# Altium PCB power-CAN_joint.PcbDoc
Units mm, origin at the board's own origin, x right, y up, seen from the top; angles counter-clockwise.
Board outline 50 x 64 mm, 2 copper layers (Top Layer, Bottom Layer); 8 components, 5 nets, 42 pads, 3 vias.
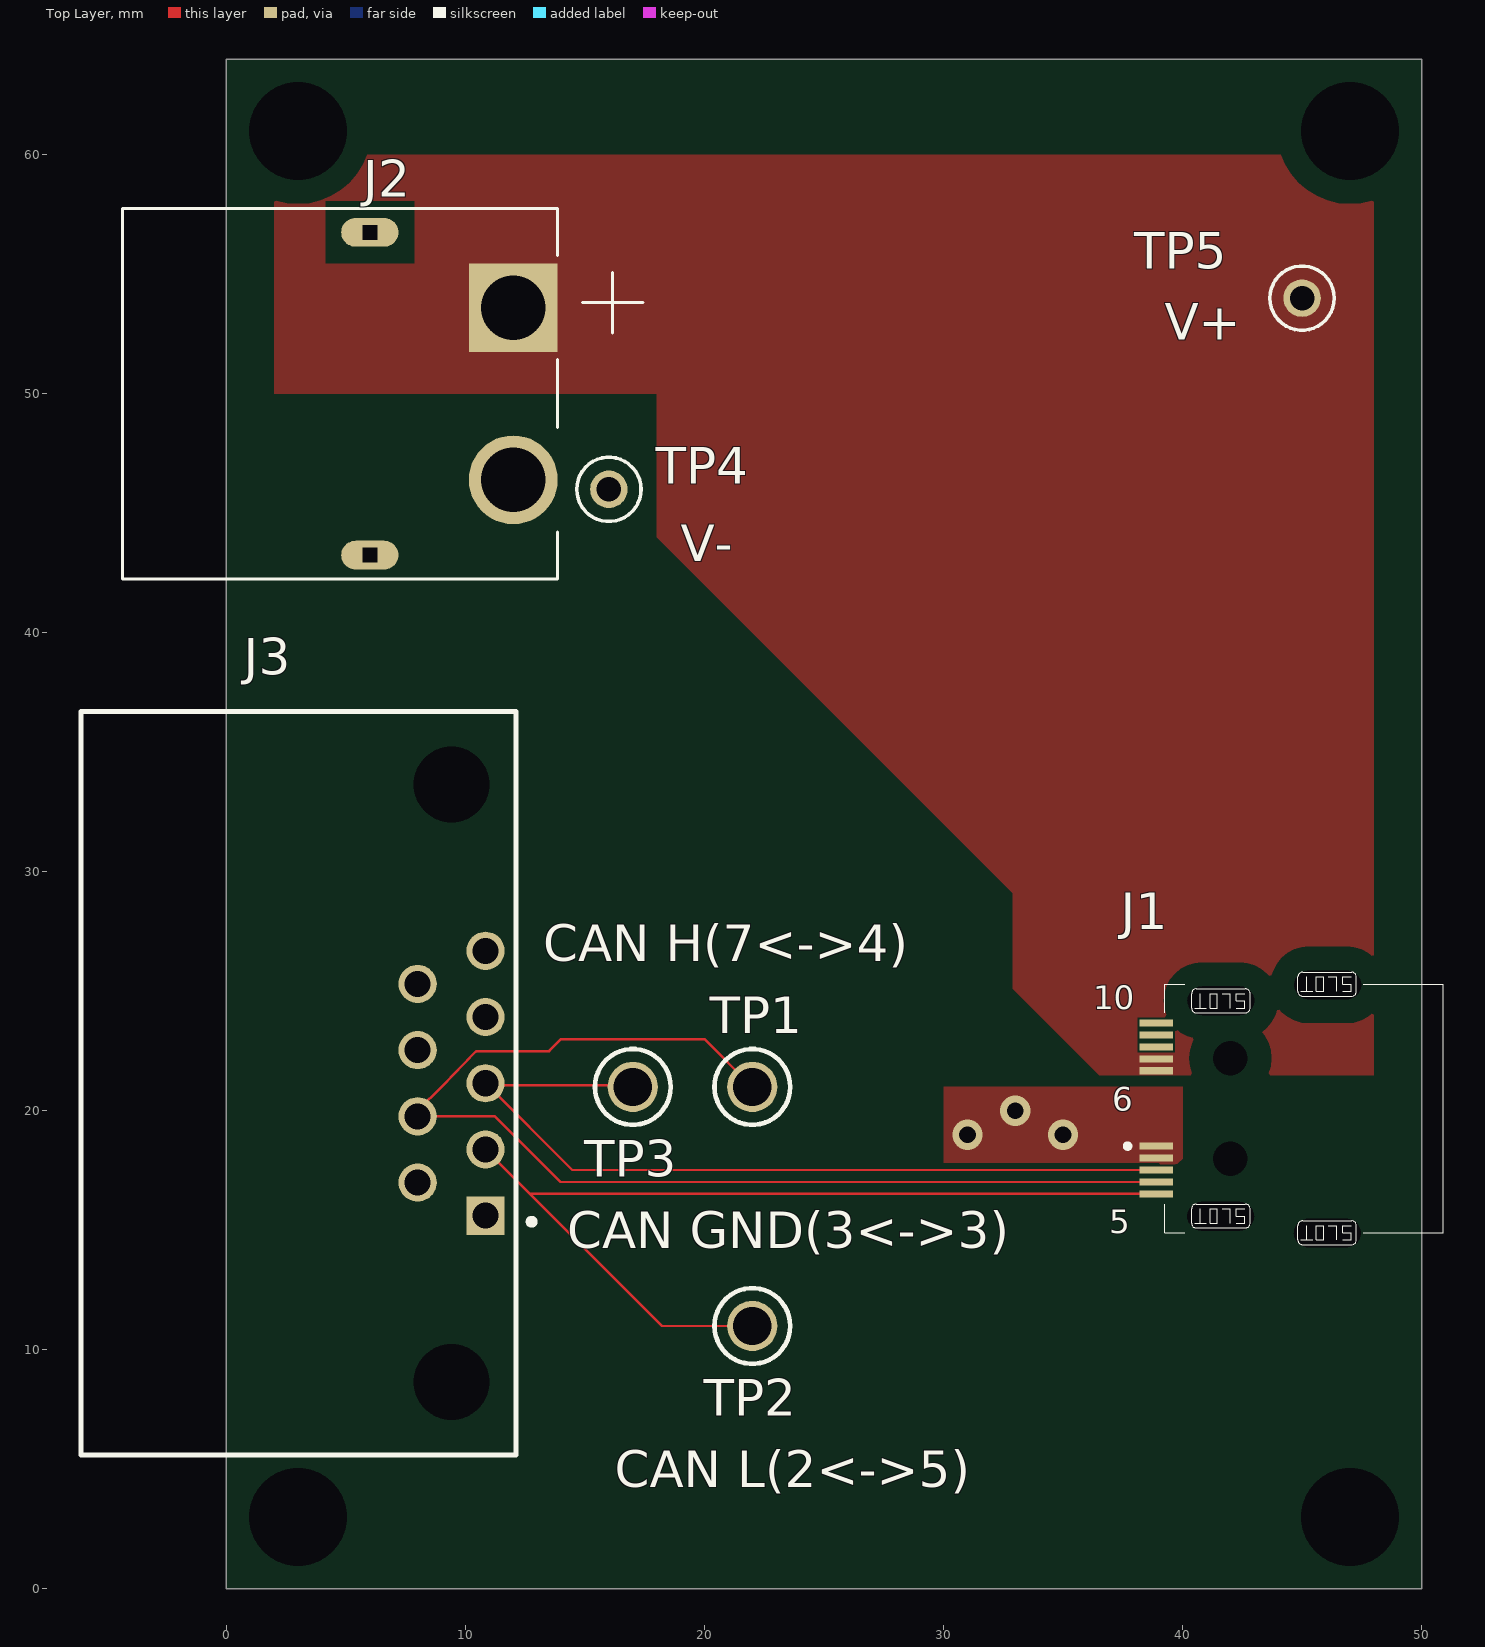
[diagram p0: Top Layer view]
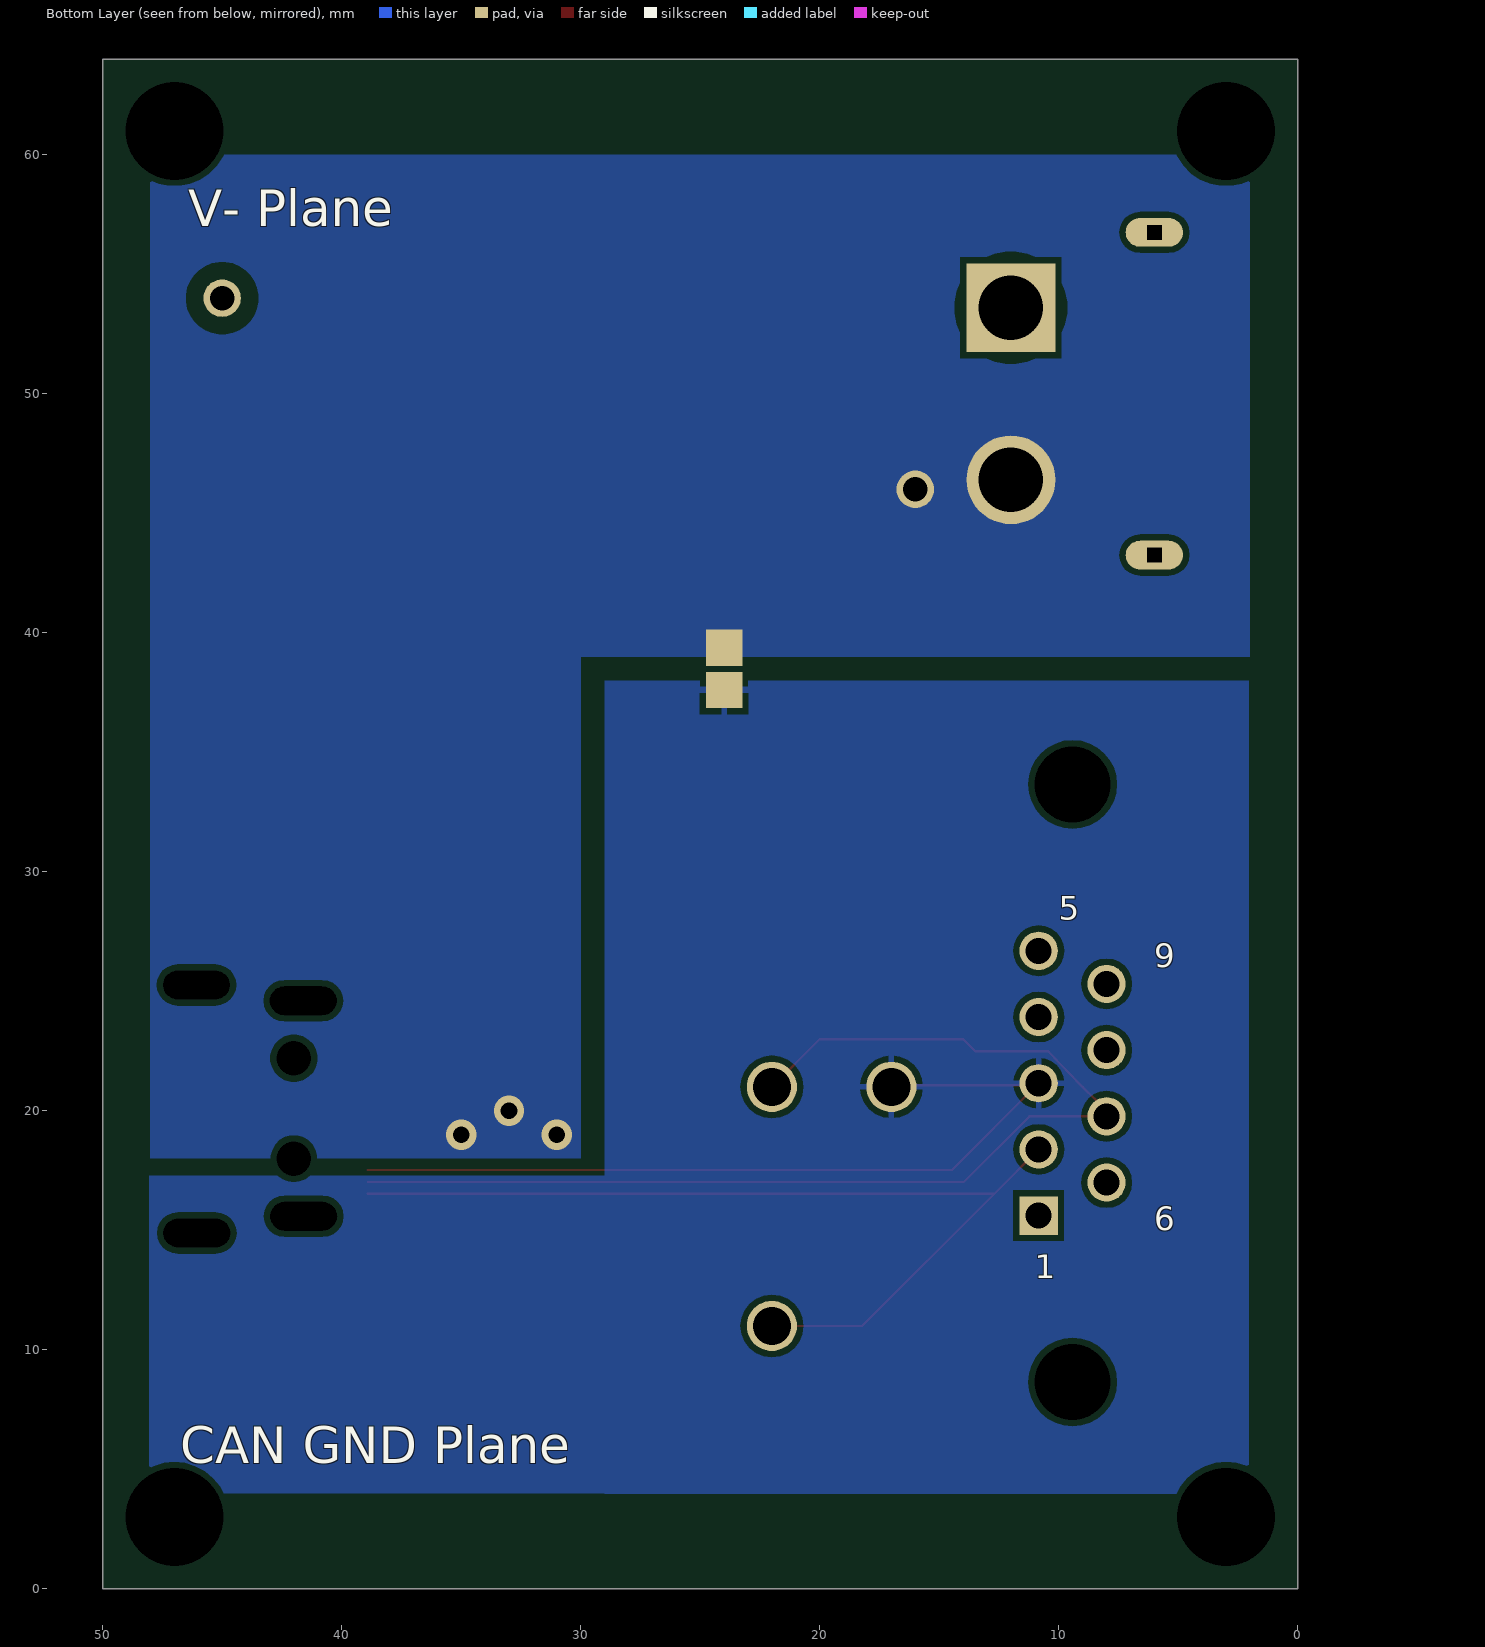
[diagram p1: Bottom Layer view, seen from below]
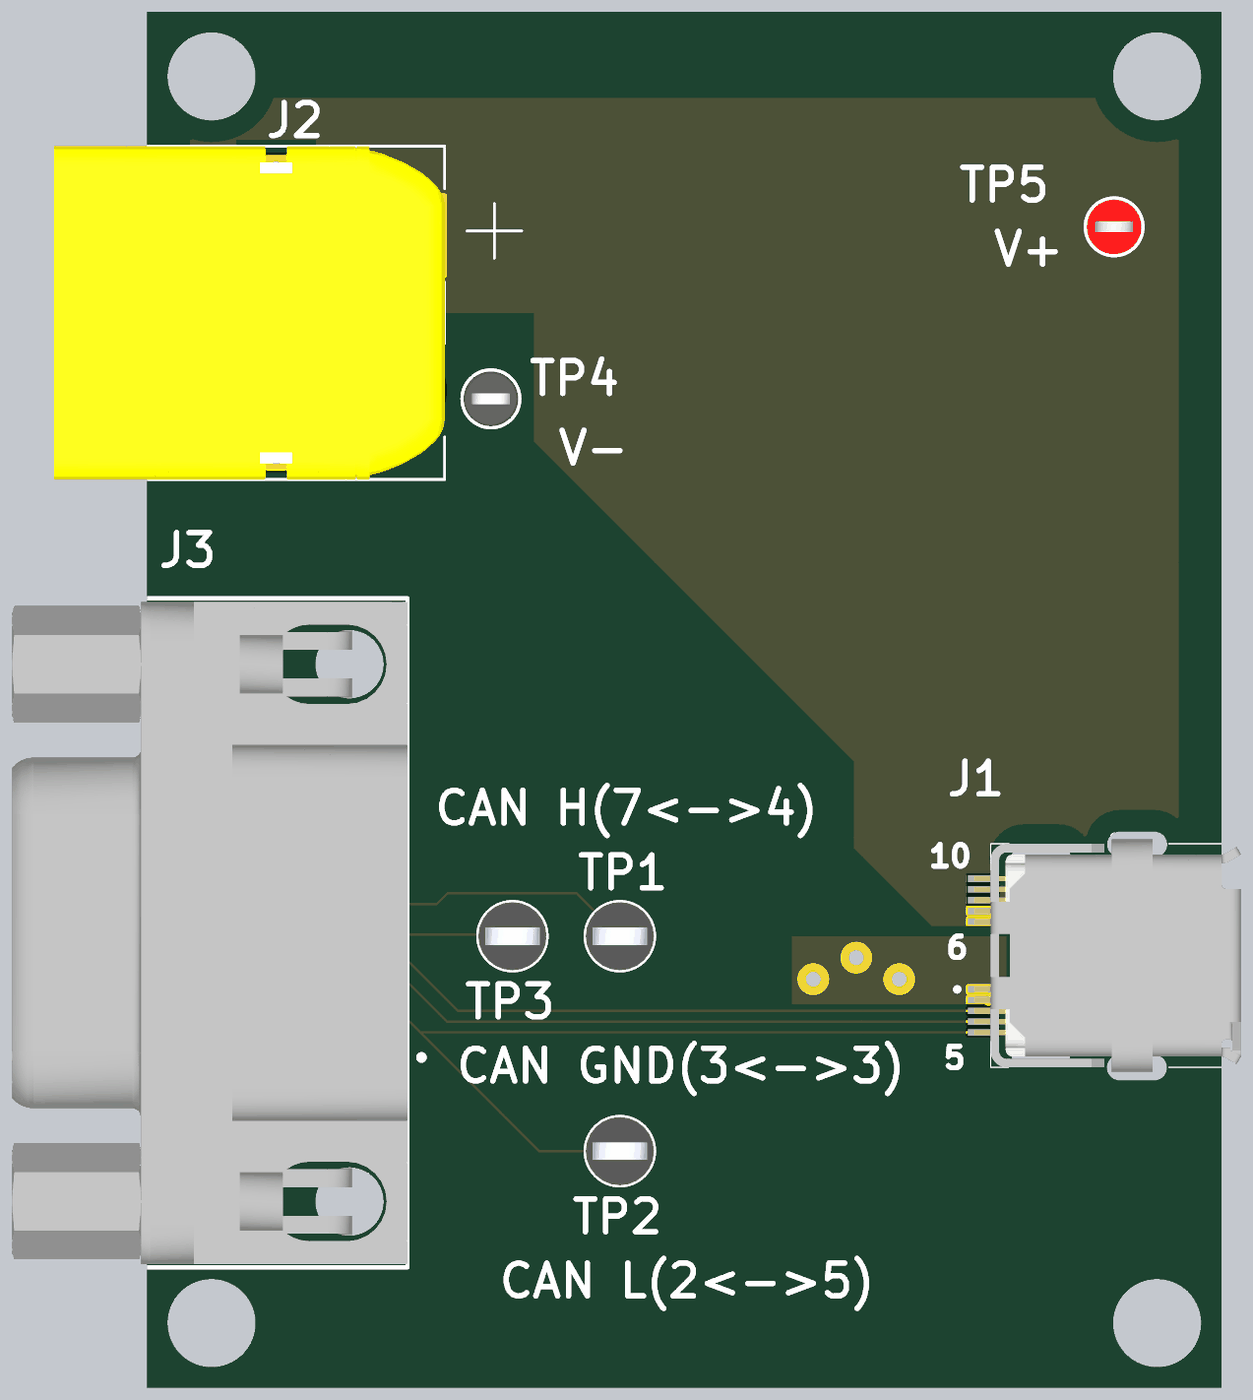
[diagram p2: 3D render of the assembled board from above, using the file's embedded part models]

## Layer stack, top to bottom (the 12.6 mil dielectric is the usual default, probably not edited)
Top Solder: solder mask 0.0254, SM-001, Dk 4
Top Layer: signal copper 0.0356
Dielectric 1: dielectric 0.32, FR-4, Dk 4.8
Bottom Layer: signal copper 0.0356
Bottom Solder: solder mask 0.0254, SM-001, Dk 4

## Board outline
0,0 50,0 50,64 0,64

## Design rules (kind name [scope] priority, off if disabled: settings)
AssemblyTestPointUsage [All] p1: isadvanced=TRUE
AssemblyTestpoint [All] p1: isadvanced=TRUE testpointundercomponent=TRUE minsize=1.016 maxsize=2.54 preferedsize=1.524 minholesize=0 maxholesize=1.016 preferedholesize=0.813 testpointgrid=0.025 usegrid=TRUE gridtolerance=0 allowsidetop=TRUE allowsidebottom=TRUE
Clearance Clearance_1 [InNet('V+') And OnMid vs OnMid] p1: gap=0.254 ignorepadtopadclearanceinfootprint=FALSE except(0.1: SMDPad-SMDPad SMDPad-THPad SMDPad-Via SMDPad-Fill SMDPad-Poly SMDPad-Region; 1: Arc-Hole Track-Hole SMDPad-Hole THPad-Hole Via-Hole Fill-Hole Poly-Hole Region-Hole Text-Hole) sourcerule=49 cellrowname=V+ cellrowtype=1 cellcolname=All cellcoltype=0 innerlayers=TRUE
Clearance Clearance_2 [InNet('V+') And (ExistsOnLayer('Top Layer') Or ExistsOnLayer('Bottom Layer')) vs (ExistsOnLayer('Top Layer') Or ExistsOnLayer('Bottom Layer'))] p2: gap=0.254 ignorepadtopadclearanceinfootprint=FALSE except(0.1: SMDPad-SMDPad SMDPad-THPad SMDPad-Via SMDPad-Fill SMDPad-Poly SMDPad-Region; 1: Arc-Hole Track-Hole SMDPad-Hole THPad-Hole Via-Hole Fill-Hole Poly-Hole Region-Hole Text-Hole) sourcerule=49 cellrowname=V+ cellrowtype=1 cellcolname=All cellcoltype=0 outerlayers=TRUE
Clearance Clearance_3 [InNet('V+')] p3: gap=0.254 ignorepadtopadclearanceinfootprint=FALSE sourcerule=49 cellrowname=V+ cellrowtype=1 cellcolname=All cellcoltype=0
Clearance Clearance_1 [InNet('V-') And OnMid vs OnMid] p4: gap=0.254 ignorepadtopadclearanceinfootprint=FALSE except(0.1: Arc-SMDPad Track-SMDPad SMDPad-SMDPad SMDPad-THPad SMDPad-Via SMDPad-Fill SMDPad-Poly SMDPad-Region SMDPad-Text) sourcerule=49 cellrowname=V- cellrowtype=1 cellcolname=All cellcoltype=0 innerlayers=TRUE
Clearance Clearance_2 [InNet('V-') And (ExistsOnLayer('Top Layer') Or ExistsOnLayer('Bottom Layer')) vs (ExistsOnLayer('Top Layer') Or ExistsOnLayer('Bottom Layer'))] p5: gap=0.254 ignorepadtopadclearanceinfootprint=FALSE except(0.1: Arc-SMDPad Track-SMDPad SMDPad-SMDPad SMDPad-THPad SMDPad-Via SMDPad-Fill SMDPad-Poly SMDPad-Region SMDPad-Text) sourcerule=49 cellrowname=V- cellrowtype=1 cellcolname=All cellcoltype=0 outerlayers=TRUE
Clearance Clearance_3 [InNet('V-')] p6: gap=0.254 ignorepadtopadclearanceinfootprint=FALSE sourcerule=49 cellrowname=V- cellrowtype=1 cellcolname=All cellcoltype=0
Clearance Clearance_1 [OnMid vs OnMid] p7: gap=0.254 ignorepadtopadclearanceinfootprint=FALSE except(0.1: Arc-SMDPad Track-SMDPad SMDPad-SMDPad SMDPad-THPad SMDPad-Via SMDPad-Fill SMDPad-Poly SMDPad-Region SMDPad-Text) sourcerule=49 cellrowname=All cellrowtype=0 cellcolname=All cellcoltype=0 innerlayers=TRUE
Clearance Clearance_2 [(ExistsOnLayer('Top Layer') Or ExistsOnLayer('Bottom Layer')) vs (ExistsOnLayer('Top Layer') Or ExistsOnLayer('Bottom Layer'))] p8: gap=0.254 ignorepadtopadclearanceinfootprint=FALSE except(0.1: Arc-SMDPad Track-SMDPad SMDPad-SMDPad SMDPad-THPad SMDPad-Via SMDPad-Fill SMDPad-Poly SMDPad-Region SMDPad-Text) sourcerule=49 cellrowname=All cellrowtype=0 cellcolname=All cellcoltype=0 outerlayers=TRUE
Clearance [All] p9: gap=0.254 ignorepadtopadclearanceinfootprint=FALSE ismatrix=TRUE miname0=V- mitype0=1 miname1=V+ mitype1=1
ComponentClearance [All] p1: isadvanced=TRUE gap=0.254 collisioncheckmode=3 verticalgap=0.254 showdistances=FALSE
FabricationTestPointUsage [All] p1: isadvanced=TRUE valid=0 allowmultiple=FALSE
FabricationTestpoint [All] p1: isadvanced=TRUE side=3 testpointundercomponent=TRUE minsize=1.016 maxsize=2.54 preferedsize=1.524 minholesize=0 maxholesize=1.016 preferedholesize=0.813 testpointgrid=0.025 allowsidetop=TRUE allowsidebottom=TRUE usegrid=TRUE gridtolerance=0
FanoutControl Fanout_BGA [IsBGA] p1: isadvanced=TRUE bgadir=Out bgaviamode=Centered fanoutstyle=Auto fanoutdirection=Alternating viagrid=0.025 // Fanout_BGA (Default Rule)
FanoutControl Fanout_LCC [IsLCC] p2: isadvanced=TRUE bgadir=Out bgaviamode=Centered fanoutstyle=Auto fanoutdirection=Alternating viagrid=0.025 // Fanout_LCC (Default Rule)
FanoutControl Fanout_SOIC [IsSOIC] p3: isadvanced=TRUE bgadir=Out bgaviamode=Centered fanoutstyle=Auto fanoutdirection=Alternating viagrid=0.025 // Fanout_SOIC (Default Rule)
FanoutControl Fanout_Small [(CompPinCount < 5)] p4: isadvanced=TRUE bgadir=Out bgaviamode=Centered fanoutstyle=Auto fanoutdirection=OutThenIn viagrid=0.025 // Fanout_Small (Default Rule)
FanoutControl Fanout_Default [All] p5: isadvanced=TRUE bgadir=Out bgaviamode=Centered fanoutstyle=Auto fanoutdirection=Alternating viagrid=0.025 // Fanout_Default (Default Rule)
Height [All] p1: isadvanced=TRUE minheight=0 maxheight=25.4 prefheight=12.7
HoleSize [All] p1: isadvanced=TRUE absolutevalues=TRUE maxlimit=10 minlimit=0.025 maxpercent=80.000 minpercent=20.000
HoleToHoleClearance [All] p1: isadvanced=TRUE gap=0.254 allowstackedmicrovias=TRUE
LayerPairs [All] p1: isadvanced=TRUE enforce=TRUE
MinimumSolderMaskSliver [All] p1: isadvanced=TRUE minsoldermaskwidth=0.254
NetAntennae [All] p1: isadvanced=TRUE netantennaetolerance=0
PasteMaskExpansion [All] p1: isadvanced=TRUE expansion=0
PlaneClearance [All] p1: isadvanced=TRUE clearance=0.508
PlaneConnect [All] p1: isadvanced=TRUE planeconnectstyle=Relief reliefexpansion=0.508 reliefentries=4 reliefconductorwidth=0.254 reliefairgap=0.254
PolygonConnect PolygonConnectStyle_2 [InNet('V+')] p1: connectstyle=Direct reliefconductorwidth=0.254 reliefentries=4 polygonreliefangle="90 Angle" airgapwidth=0.254
PolygonConnect PolygonConnectStyle_1 [InNet('V-')] p2: connectstyle=Direct reliefconductorwidth=0.254 reliefentries=4 polygonreliefangle="90 Angle" airgapwidth=0.254
PolygonConnect PolygonConnectStyle_3 [InNet('CAN_GND')] p3: connectstyle=Relief reliefconductorwidth=0.254 reliefentries=4 polygonreliefangle="90 Angle" airgapwidth=0.254
PolygonConnect [All] p4: connectstyle=Relief reliefconductorwidth=0.254 reliefentries=4 polygonreliefangle="90 Angle" airgapwidth=0.254
RoutingCorners [All] p1: isadvanced=TRUE cornerstyle=45-Degree minsetback=2.54 maxsetback=2.54
RoutingPriority [All] p1: isadvanced=TRUE routingpriority=0
RoutingVias [All] p1: holewidth=0.7 width=1.27 viastyle="Through Hole" minholewidth=0.7 minwidth=1.27 maxholewidth=0.7 maxwidth=1.27
ShortCircuit [All] p1: isadvanced=TRUE allowed=FALSE
SilkToSilkClearance [All] p1: isadvanced=TRUE silktosilkclearance=0.254
SilkToSolderMaskClearance [IsPad] p1: isadvanced=TRUE minsilkscreentomaskgap=0.254 clearancetoexposedcopper=TRUE
SolderMaskExpansion [All] p1: isadvanced=TRUE expansion=0.102 istentingtop=FALSE
SupplyNets "Schematic Supply Nets_1" [InNet('V-')] p1: isadvanced=TRUE voltage=0.000
SupplyNets "Schematic Supply Nets" [InNet('V+')] p2: isadvanced=TRUE voltage=0.000
UnRoutedNet [All] p1: isadvanced=TRUE
UnpouredPolygon [All] p1: isadvanced=TRUE
Width "Schematic Width Constraint_1" [InNet('V+')] p1: maxlimit=10 minlimit=0.09 preferedwidth=0.1 minimp=50.000000 maximp=50.000000 favimp=50.000000
Width "Schematic Width Constraint" [InNet('V-')] p2: maxlimit=10 minlimit=0.09 preferedwidth=0.1 minimp=50.000000 maximp=50.000000 favimp=50.000000
Width [All] p3: maxlimit=0.1 minlimit=0.09 preferedwidth=0.1 minimp=50.000000 maximp=50.000000 favimp=50.000000
4 further rules are at their usual default settings.

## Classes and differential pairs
component class power-CAN_joint: J2 TP1 TP2 TP3 TP4

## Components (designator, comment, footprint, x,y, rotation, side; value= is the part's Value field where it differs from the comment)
J1 "09452819001" 09452812561 41.6,20.1 r90 top
J2 "XT60PW-M" AMASS_XT60PW-M 6,50 r90 top
J3 "2311765-1" TECO-2311765-1_V 9.42,21.155 r90 top locked
TP1 "5011" KSTN-5011_V 22,21 r0 top
TP2 "5011" KSTN-5011_V 22,11 r0 top
TP3 "5011" KSTN-5011_V 17,21 r0 top
TP4 "5001" FP-5001-MFG 16,46 r0 top (schematic designator J5)
TP5 "5000" FP-5000-MFG 45,54 r0 top (schematic designator J4)

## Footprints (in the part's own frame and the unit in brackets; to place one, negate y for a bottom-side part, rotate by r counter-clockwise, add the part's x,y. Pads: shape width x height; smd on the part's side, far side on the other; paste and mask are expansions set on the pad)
09452812561 [mm]
  rect 0.3x1.4 smd: 1(-1.575,2.7) 2(-2.075,2.7) 3(-2.575,2.7) 4(-3.075,2.7) 5(-3.575,2.7) 6(1.575,2.7) 7(2.075,2.7) 8(2.575,2.7) 9(3.075,2.7) 10(3.575,2.7)
  round 0.725 hole 1.45 unplated: 11(-2.1,-0.4) 12(2.1,-0.4)
  silkscreen extent -5.7,-9.3 5.7,4, body extent -5.4,-9.3 5.4,3.1, height 5.78
AMASS_XT60PW-M [mm]
  rect 3.716x3.716 / inner round 3.716 / far side rect 3.716x3.716 hole 2.7: 1(3.6,-6)
  round 3.716 hole 2.7: 2(-3.6,-6)
  oval 1.2x2.4 hole 0.6 square: S1(6.75,0) S2(-6.75,0)
  silkscreen extent -7.75,-11.43 7.75,10.35, body extent -7.75,-7.85 7.75,10.35, height 8.4
FP-5000-MFG [mm]
  round 1.57 hole 1.02 paste-2539.97 mask+0: 1(0,0)
  silkscreen extent -1.35,-1.34 1.35,1.34, body extent -1.45,-1.45 1.45,1.45, height 0.25
FP-5001-MFG [mm]
  round 1.57 hole 1.016 paste-2539.97 mask+0: 1(0,0)
  silkscreen extent -1.35,-1.34 1.35,1.34, body extent -1.45,-1.45 1.45,1.45, height 0.25
KSTN-5011_V [mm] "Test Point, Dia 3.17mm"
  round 2.1 hole 1.6: 1(0,0)
  silkscreen extent -1.59,-1.58 1.59,1.58, body extent -1.59,-1.59 1.59,1.59, height 8.13
TECO-2311765-1_V [mm] "TH, 9-Leads, Body 30.81x18.2mm, Pitch 2.77mm"
  rect 1.6x1.6 hole 1.09: 1(-5.54,-1.42)
  round 1.6 hole 1.09: 2(-2.77,-1.42) 3(0,-1.42) 4(2.77,-1.42) 5(5.54,-1.42) 6(-4.155,1.42) 7(-1.385,1.42) 8(1.385,1.42) 9(4.155,1.42)
  round 0 hole 3.18 unplated: MH1(-12.5,0) MH2(12.5,0)
  silkscreen extent -15.56,-3.48 15.56,15.5, body extent -15.4,-2.7 15.4,15.72, height 12.5

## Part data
J1: "Connector", Manufacturer_Name=HARTING, Mouser Part Number=617-09452819001
J2: library part CMP-002-000000-1, "Socket, DC supply, male, PIN: 2", Package=Package
J3: library part CMP-2000-07623-1, "D-Sub Receptacle, Pitch 2.77 mm, 1 x 9 Position, Height 12.55 mm, -55 to 105 degC, RoHS", Manufacturer=TEConnectivity, Package Description="D-Sub Receptacle, Pitch 2.77 mm, 1 x 9 Position, Height 12.55 mm"
TP1 TP2 TP3: library part CMP-1672-00003-4, "Test Point, Black, Through Hole, RoHS, Bulk", Colour=Black, Manufacturer=Keystone, Package Quantity=100
TP4: library part CMP-2000-05181-2, "PC TEST POINT MINIATURE BLACK", Color=Black, Flammability Rating="UL94 V-0", Package Quantity=100
TP5: library part CMP-19636-000027-1, "PC TEST POINT MINIATURE RED", Color=Red, Flammability Rating="UL94 V-0", Package Quantity=100

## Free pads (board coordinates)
  round 0 hole 1.2 slot 2.8 at 0 deg unplated: 2(41.59,15.59) 2(41.603,24.605) 2(46.059,14.888) 2(46.072,25.267)
  rect 1.524x1.524 smd far side mask+0.2: 4(23.998,39.375) 5(23.997,37.604)
  round 0 hole 4.1 unplated: 7777(3,3) 7777(3,61) 7777(47,3) 7777(47,61)

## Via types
v1: diameter 1.27, hole 0.7, Top Layer to Bottom Layer, 3 vias

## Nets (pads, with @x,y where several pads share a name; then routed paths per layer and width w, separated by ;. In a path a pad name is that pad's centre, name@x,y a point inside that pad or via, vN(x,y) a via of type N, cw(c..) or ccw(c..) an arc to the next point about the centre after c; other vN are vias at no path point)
CAN_GND: J1.3 J3.3 pad.5 TP3.1 | length 35.7
  Top Layer w0.1: J3.3 J3.3@10.917,21.078 ; TP3.1 16.922,21.078 J3.3@10.917,21.078 ; J1.3 14.47,17.525 J3.3@10.917,21.078
CAN_H: J1.4 J3.7 TP1.1 | length 48.4
  Top Layer w0.1: 10.425,22.47 9.025,21.025 cw(c8.231,21.792) 9,21 8.03,20.059 8,20.029 J3.7 11.23,19.77 13.975,17.025 J1.4 ; 10.425,22.471 10.454,22.5 13.5,22.5 14,23 20,23 TP1.1
CAN_L: J1.5 J3.2 TP2.1 | length 40.4
  Top Layer w0.1: J3.2 12.7,16.525 ; TP2.1 18.225,11 12.7,16.525 ; J1.5 12.7,16.525
V+: J1.6 J1.7 J2.1 TP5.1
V-: J1.1 J1.2 J2.2 pad.4 TP4.1 | length 0.5
  Top Layer w2: J2.2 J2.2@12.328,46.072
  other v1: 31,19 35,19 33,20
pads on no net: J1.8 J1.9 J1.10 J1.11 J1.12 J2.S1 J2.S2 J3.1 J3.4 J3.5 J3.6 J3.8 J3.9 J3.MH1 J3.MH2

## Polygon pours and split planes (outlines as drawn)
CAN_GND on Bottom Layer "22" (solid, pour order 17): 2.045,3.982 28.996,3.982 28.996,4 48.045,4 48.045,17.291 28.996,17.291 28.996,38 2.045,38
V- on Bottom Layer "V-_L02_P018" (solid, pour order 18): 30,18.025 30,40 48,40 48,18.025
V- on Bottom Layer "3" (solid, pour order 0): 2,60 48,60 48,39 2,39
V- on Top Layer "V-_L01_P022" (solid, pour order 22): 30,21 30,17.676 39.676,17.676 40,18 40,21
V+ on Top Layer "V+_L01_P021" (solid, pour order 21): 37.872,22.32 40.046,22.32 40.222,22.144 40.078,22 38,22
V+ on Top Layer "Top Layer-V+" (solid, pour order 12): 32.889,25.111 36.521,21.479 48,21.479 48,60 2,60 2,50 18,50 18,44 32.889,29.111

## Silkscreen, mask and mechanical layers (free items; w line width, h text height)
Top Overlay:
  text "V+" at 39.254,52.254 h1.52
  text "V-" at 19,43 h1.52
  text "CAN H(7<->4)" at 13.254,26.254 h1.52
  text "10" at 36.254,24.254 h1
  text "6" at 37.049,19.999 h1
  text "5" at 36.927,14.869 h1
  text "CAN GND(3<->3)" at 14.254,14.254 h1.52
  text "CAN L(2<->5)" at 16.254,4.254 h1.52
Bottom Overlay:
  text "V- Plane" at 46.422,57.012 h1.52
  text "5" at 10,28 h1
  text "9" at 6,26 h1
  text "6" at 6,15 h1
  text "1" at 11,13 h1
  text "CAN GND Plane" at 46.746,5.254 h1.52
